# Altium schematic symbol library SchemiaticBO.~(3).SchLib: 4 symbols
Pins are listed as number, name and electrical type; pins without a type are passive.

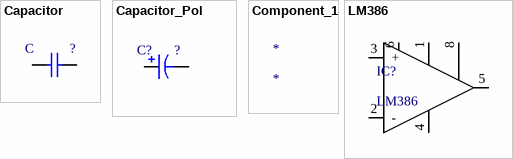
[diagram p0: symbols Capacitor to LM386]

## Capacitor
designator C  (value not drawn)
footprint CAP_MKT_2.5x6.5x7.2 (Raster 5)
footprint CAP_MKT_5x10x7.2 (Raster 5)
footprint CAP_MKT_3.5x8.5x7.2 (Raster 5)
footprint CAP_MLCC (Raster 5)
footprint CAP_MKT_3x7.5x7.2 (Raster 5)
footprint CAP SMD 1x0.5x0.5
footprint CAP SMD 1.6x0.8x0.8
footprint CAP SMD 2x1.25x1.25
footprint CAP SMD 3.2x1.6x1.6
pins: 1, 2

## Capacitor_Pol
designator C?  (value not drawn)
footprint Panasonic_K16_BO
footprint CAP_POL_s16x25 (Raster 7.5)
footprint CAP_POL_s10x20 (Raster 5)
footprint CAP_POL_s10x16 (Raster 5)
footprint CAP_POL_s6.3x11 (Raster 2.5)
footprint CAP_POL_s5x11 (Raster 2)
footprint CAP_POL_SMD_8.5x8.5x10.7
footprint CAP_POL_SMD_6.8x6.8x8
footprint CAP_POL_SMD_6.8x6.8x6
footprint CAP_POL_SMD_4.5x4.5x6
pins: 1, 2

## Component_1
designator *

## LM386
designator IC?
footprint SO8_BO
pins: 1, 2 -, 3 +, 4, 5, 6, 8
